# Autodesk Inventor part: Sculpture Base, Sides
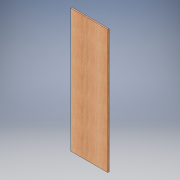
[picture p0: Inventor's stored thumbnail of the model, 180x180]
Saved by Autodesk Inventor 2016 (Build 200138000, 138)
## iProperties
Created: 2015-08
Part Number: Sculpture Base, Sides
Material: Wood (Birch)
Document SubType Name: Modeling
Designer: Chris Eckert
Density: 0.55 g/cm^3
Appearance: Birch - Natural Polished
Author: Chris Eckert
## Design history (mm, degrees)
sketch "Sketch1"
  geometry: L1 (-177.8, 596.9)-(177.8, 596.9); L2 (177.8, 596.9)-(177.8, -596.9); L3 (177.8, -596.9)-(-177.8, -596.9); L4 (-177.8, -596.9)-(-177.8, 596.9); 1 further point
  constraints: 8 end point, 2 parallel, 1 horizontal, 1 perpendicular
  dimensions: "d0" = 1193.8 distance of L3.end L1.start (= OverallHeight); "d1" = 355.6 distance of L1.start L1.end (= OverallWidth - WoodThickness); "d2" = 177.8 distance from line of L4 point (0, 0) (= 0.5 x d1); "d3" = 596.9 distance from line of L1 point (0, 0) (= 0.5 x d0)
extrude "Extrusion1" new body sketch "Sketch1" distance "d4" = 12.7 (= WoodThickness); taper "d5" = 0 deg
body "Solid1"
other parameters: "WoodThickness" = 12.7 [user parameter; used in 2 equation terms], "OverallHeight" = 1193.8 [user parameter; used in 1 equation term], "OverallWidth" = 368.3 [user parameter; used in 1 equation term], "OverallDepth" = 368.3 [user parameter], "DatoOverhang" = 1.5875 [user parameter]
